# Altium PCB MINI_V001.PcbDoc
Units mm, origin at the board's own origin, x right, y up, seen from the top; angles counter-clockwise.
Board outline 42.31 x 45.25 mm, 2 copper layers (Top Layer, Bottom Layer); 51 components, 48 nets, 206 pads, 51 vias.
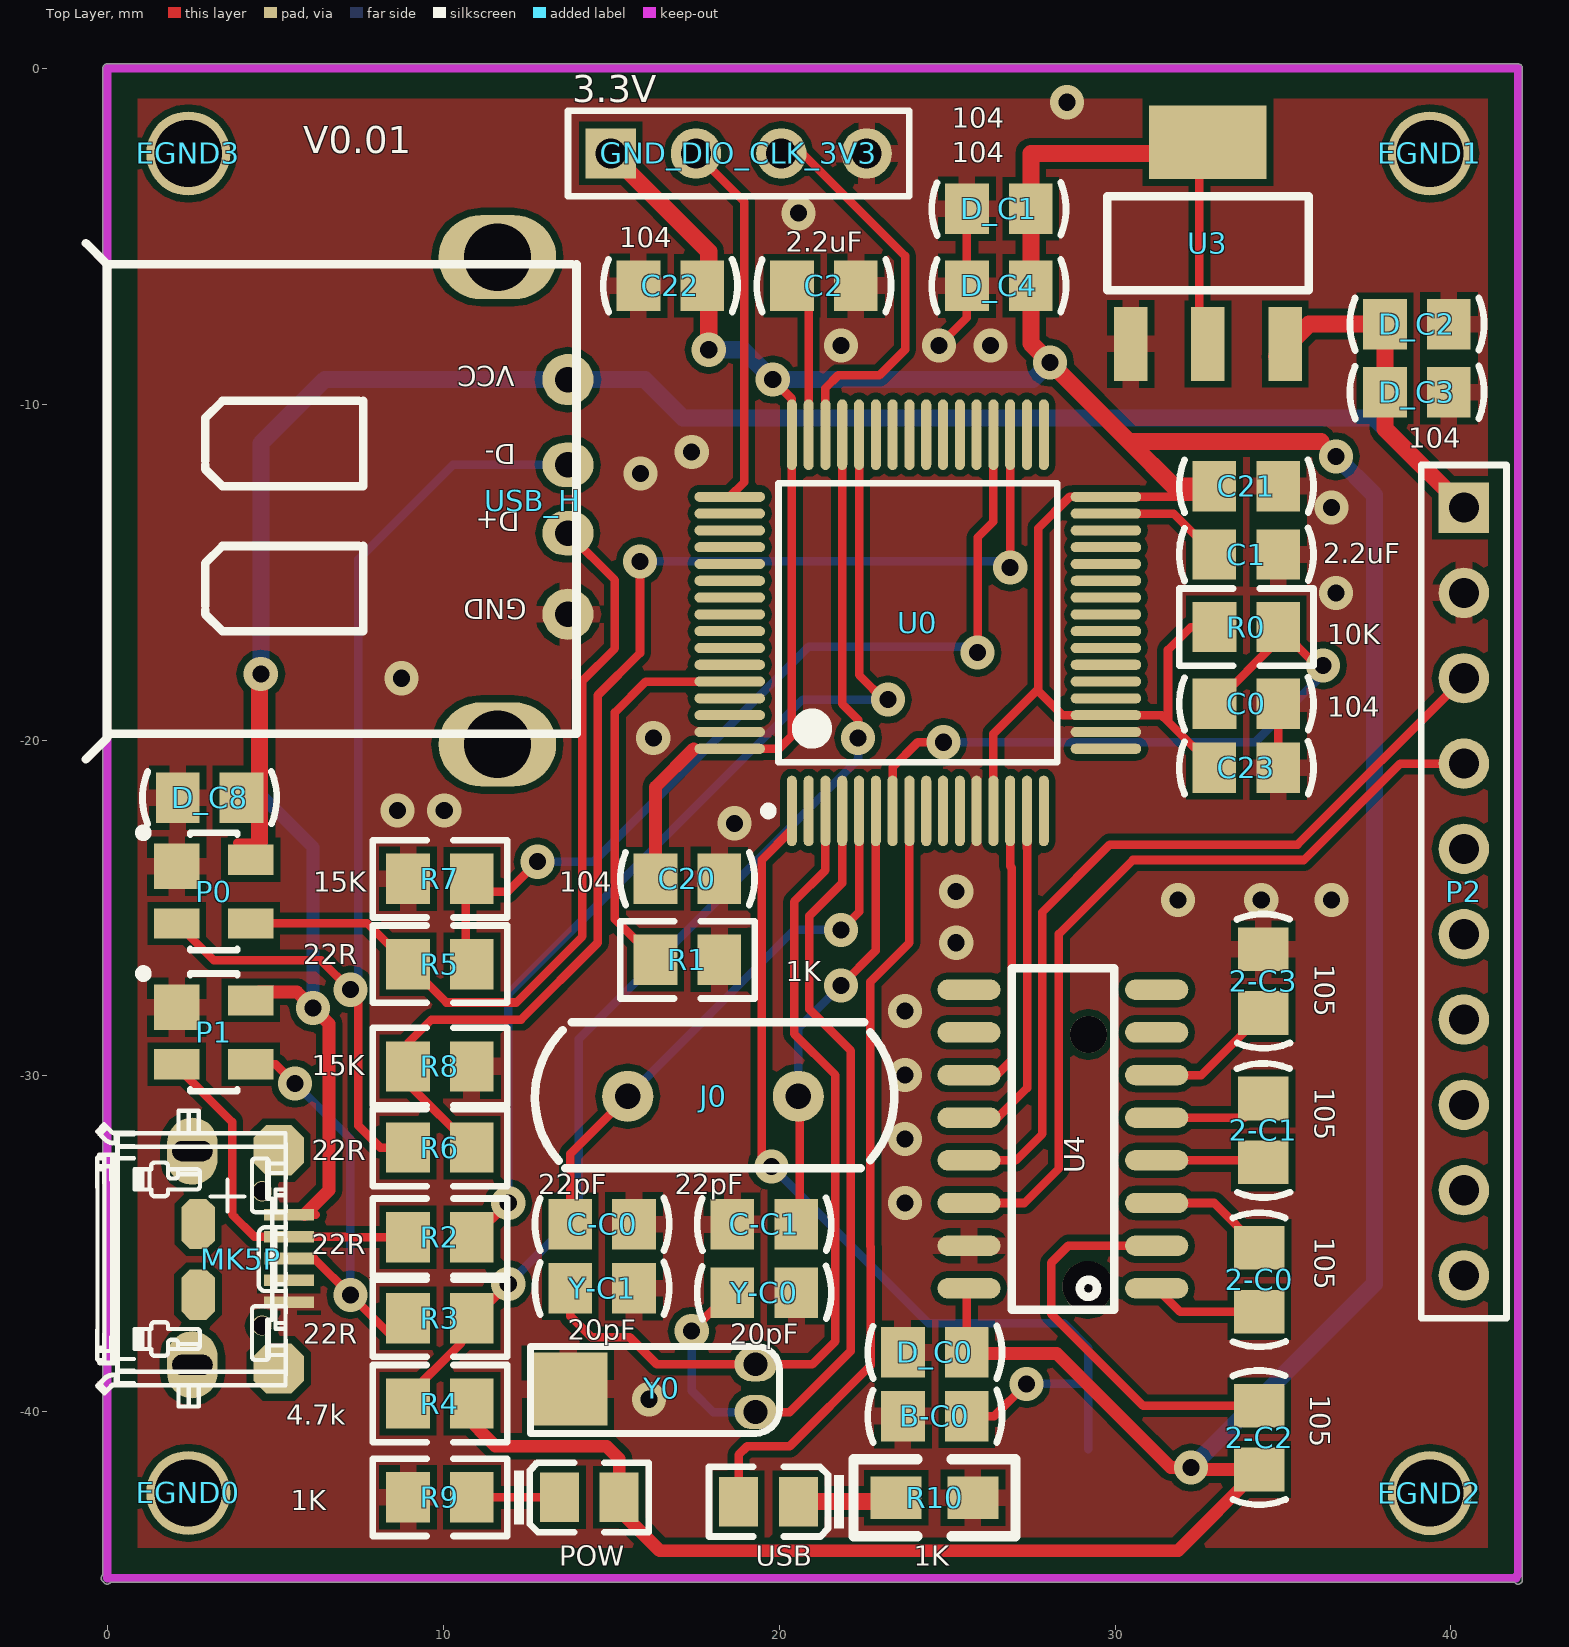
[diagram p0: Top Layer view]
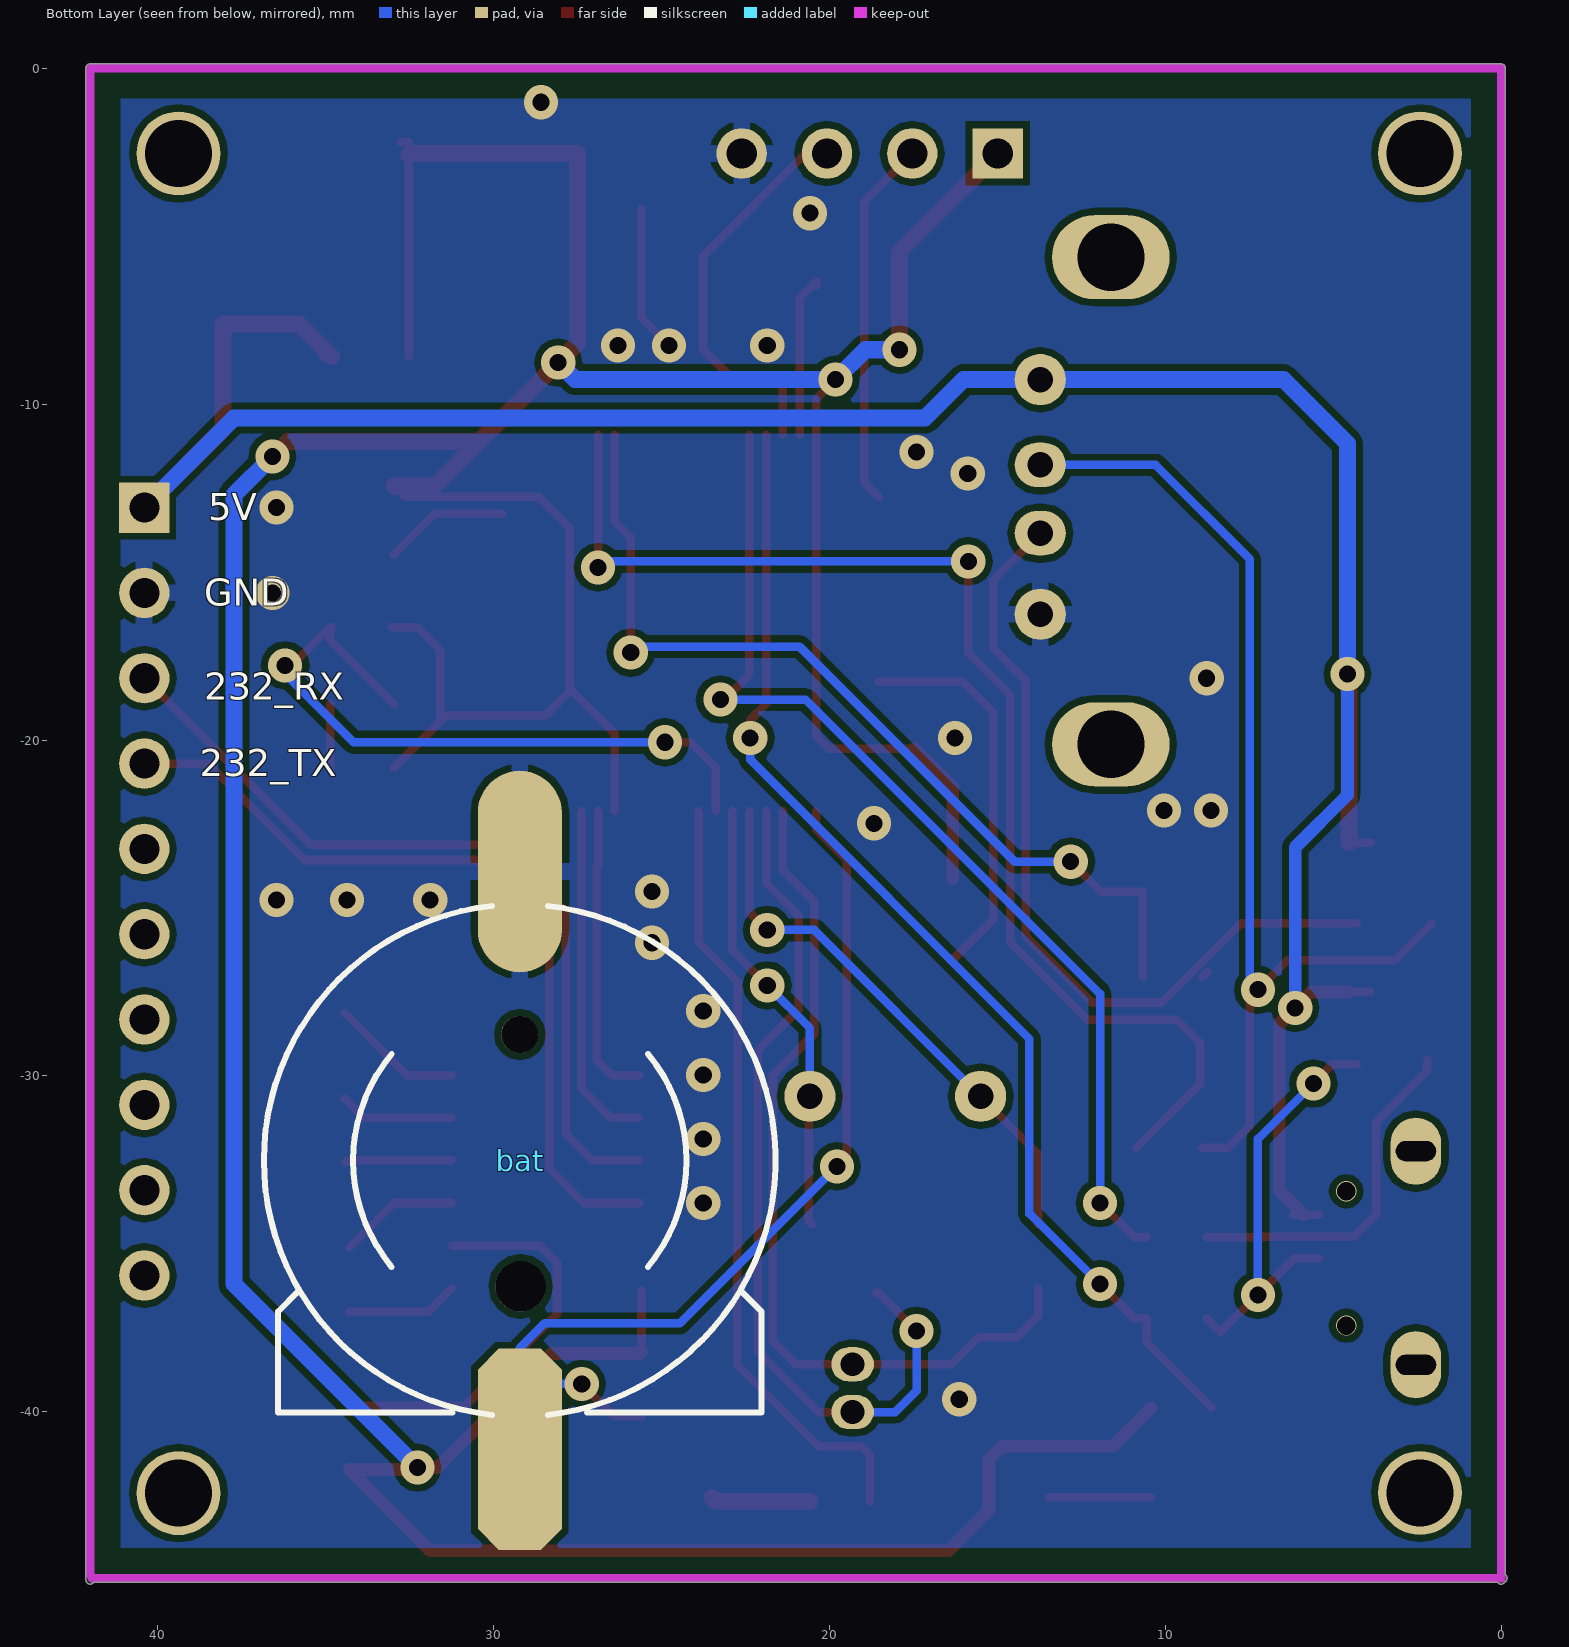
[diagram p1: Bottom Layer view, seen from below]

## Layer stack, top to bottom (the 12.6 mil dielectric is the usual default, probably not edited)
Top Layer: signal copper 0.0356
Dielectric: dielectric 0.32, FR-4, Dk 4.8
Bottom Layer: signal copper 0.0356

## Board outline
-0.112,-45.061 cw(c-0.051,-44.949) -0.127,-44.847 -0.127,0 cw(c0,0) 0,0.127 42,0.127 cw(c42,0) 42.127,0 42.127,-45 cw(c42,-45) 41.898,-45.077 0.102,-45.077 cw(c0,-45)

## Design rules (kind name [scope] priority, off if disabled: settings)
Clearance Clearance_keepout [(OnLayer('Keep-Out Layer'))] p1: gap=0.762
Clearance Clearance_ploy [inpoly] p2: gap=0.203
Clearance [All] p3: gap=0.152
ComponentClearance [All] p1: gap=0.127 collisioncheckmode=3 verticalgap=0.254 showdistances=FALSE
DiffPairsRouting DiffPair_DiffPairsRouting [InDifferentialPair ('VOUT2')] p1: maxlimit=0.254 minlimit=0.254 mostfreqgap=0.254 maxuncoupledlength=12.7
DiffPairsRouting [All] p2: maxlimit=0.254 minlimit=-0.044 mostfreqgap=0.254 toplayer_maxgap=-0.044 toplayer_prefgap=3.693 bottomlayer_maxgap=-0.044 bottomlayer_prefgap=2.348 maxuncoupledlength=12.7
HoleSize [All] p1: absolutevalues=TRUE maxlimit=5 minlimit=0.025 maxpercent=80.000 minpercent=20.000
HoleSize FabricationTestpoint [All] p2: absolutevalues=TRUE maxlimit=2.54 minlimit=0.025 maxpercent=80.000 minpercent=20.000
HoleSize FabricationTestPointUsage [All] p3: absolutevalues=TRUE maxlimit=2.54 minlimit=0.025 maxpercent=80.000 minpercent=20.000
Length [All] p1: maxlimit=152.4 minlimit=0
MatchedLengths DiffPair_MatchedLengths [InDifferentialPair ('VOUT2')] p1: tolerance=25.4 checknetsindiffpair=TRUE checkdiffpairvsdiffpair=TRUE checkothers=TRUE
MinimumSolderMaskSliver [All] p1: minsoldermaskwidth=0
MinimumSolderMaskSliver SilkToSolderMaskClearance [IsPad] p2: minsoldermaskwidth=0.254
NetAntennae AssemblyTestpoint [All] p1: netantennaetolerance=0
NetAntennae [All] p2: netantennaetolerance=0
NetAntennae AssemblyTestPointUsage [All] p3: netantennaetolerance=0
NetAntennae UnpouredPolygon [All] p4: netantennaetolerance=0
NetAntennae SilkToBoardRegionClearance [All] p5: netantennaetolerance=0
PlaneConnect [All] p1: planeconnectstyle=Direct reliefexpansion=0.508 reliefentries=4 reliefconductorwidth=0.254 reliefairgap=0.254
PolygonConnect PolygonConnect_VIA [ISVIA] p1: connectstyle=Direct reliefconductorwidth=0.254 reliefentries=4 polygonreliefangle="90 Angle"
PolygonConnect [All] p2: connectstyle=Relief reliefconductorwidth=0.508 reliefentries=4 polygonreliefangle="90 Angle"
RoutingVias [All] p1: holewidth=0.4 width=0.8 viastyle="Through Hole" minholewidth=0.3 minwidth=0.6 maxholewidth=1 maxwidth=2
SilkToSilkClearance [All] p1: silktosilkclearance=0
SilkscreenOverComponentPads [All] p1: minsilkscreentomaskgap=0.254
SolderMaskExpansion [All] p1: expansion=0.102
TestPointUsage [All] p1: valid=0 allowmultiple=FALSE
Testpoint [All] p1: side=15 testpointundercomponent=TRUE minsize=1.016 maxsize=2.54 preferedsize=1.524 minholesize=0 maxholesize=1.016 preferedholesize=0.813 testpointgrid=0.025 style=1023 order=0123456789
Width Width_VCC3.3 [InNet('G+3V3')] p1: maxlimit=2.54 minlimit=0.305 preferedwidth=0.305
Width DiffPair_Width [InDifferentialPair('VOUT2')] p2: maxlimit=0.254 minlimit=0.254 preferedwidth=0.254
Width [All] p3: maxlimit=2.54 minlimit=0.152 preferedwidth=0.203
16 further rules are at their usual default settings.

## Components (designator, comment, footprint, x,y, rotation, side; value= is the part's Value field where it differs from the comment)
2-C0 "105" C-RAD-0805 34.29,-36.068 r270 top
2-C1 "105" C-RAD-0805 34.417,-31.623 r270 top
2-C2 "105" C-RAD-0805 34.29,-40.767 r90 top
2-C3 "105" C-RAD-0805 34.417,-27.178 r270 top
B-C0 "C104" C-RAD-0805 24.638,-40.132 r0 top
bat "Battery" BATM 29.21,-32.512 r180 bottom
C0 "104" C-RAD-0805 33.909,-18.923 r0 top
C1 "2.2uF" C-RAD-0805 33.909,-14.478 r0 top
C2 "2.2uF" C-RAD-0805 21.336,-6.477 r0 top
C20 "104" C-RAD-0805 17.272,-24.13 r180 top
C21 "106" C-RAD-0805 33.909,-12.446 r180 top
C22 "104" C-RAD-0805 16.764,-6.477 r0 top
C23 "106" C-RAD-0805 33.909,-20.828 r180 top
C-C0 "22pF" C-RAD-0805 14.732,-34.417 r180 top
C-C1 "22pF" C-RAD-0805 19.558,-34.417 r0 top
D_C0 "106" C-RAD-0805 24.638,-38.227 r0 top
D_C1 "104" C-RAD-0805 26.543,-4.191 r0 top
D_C2 "106" C-RAD-0805 38.989,-7.62 r0 top
D_C3 "104" C-RAD-0805 38.989,-9.652 r0 top
D_C4 "104" C-RAD-0805 26.543,-6.477 r0 top (schematic designator D_C1)
D_C8 "106" C-RAD-0805 3.048,-21.717 r0 top (schematic designator D_C2)
EGND0 "1孔" HOLEx1 2.413,-42.412 r0 top
EGND1 "1孔" HOLEx1 39.37,-2.54 r0 top
EGND2 "1孔" HOLEx1 39.37,-42.418 r0 top
EGND3 "1孔" HOLEx1 2.413,-2.54 r0 top
GND_DIO_CLK_3V3 "Header 4" HDR1X4 14.986,-2.54 r0 top
J0 "25M" 晶振HC-49S 18.034,-30.607 r180 top
MK5P "五脚端子" USB-MICRO1 5.08,-35.433 r90 top
P0 "PRTR5V0U2X" SOT-143 3.175,-24.511 r270 top
P1 "PRTR5V0U2X" SOT-143 3.175,-28.702 r270 top
P2 "Header 10" HDR1X10 40.386,-13.081 r270 top
POW "Rled" 0805_LED_S1 14.351,-42.545 r0 top (schematic designator D0)
R0 "10K" R2012-0805 33.909,-16.637 r0 top
R1 "1K" R2012-0805 17.272,-26.543 r0 top
R2 "22R" R2012-0805 9.906,-34.798 r180 top
R3 "22R" R2012-0805 9.906,-37.211 r180 top
R4 "4.7k" R2012-0805 9.906,-39.751 r0 top
R5 "22R" R2012-0805 9.906,-26.67 r180 top
R6 "22R" R2012-0805 9.906,-32.131 r180 top
R7 "15K" R2012-0805 9.906,-24.13 r180 top
R8 "15K" R2012-0805 9.906,-29.718 r0 top
R9 "1K" R2012-0805 9.906,-42.545 r0 top
R10 "1K" 0805 25.781,-42.545 r180 top
U0 "STM32F205RBT6" LQFP-64 24.13,-16.51 r90 top
U3 "AMS1117-3.3" SOT-223 32.766,-5.207 r270 top
U4 "MAX3232" SOP-16 31.242,-36.322 r90 top
USB "Bled" 0805_LED_S1 19.685,-42.672 r180 top (schematic designator D1)
USB_H "五脚端子" USB 13.716,-9.271 r180 top
Y0 "32.768M" XTAL32 19.304,-40.005 r180 top
Y-C0 "20pF" C-RAD-0805 19.558,-36.449 r180 top
Y-C1 "20pF" C-RAD-0805 14.732,-36.322 r180 top

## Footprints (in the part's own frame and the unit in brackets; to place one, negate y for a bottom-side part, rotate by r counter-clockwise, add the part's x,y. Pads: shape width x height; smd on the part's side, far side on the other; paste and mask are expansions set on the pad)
0805 [mil]
  rect 60x50 smd: 1(0.41,0.4) 2(90.41,0.4)
  silkscreen extent -50,-45 140,45
0805_LED_S1 [mm]
  rect 1.16x1.47 smd: A(0.89,0) K(-0.89,0)
  silkscreen extent -2.25,-1.03 1.77,1.03, body extent -1.01,-0.62 1.01,0.62, height 1.1
BATM [mm]
  round 1.1 hole 1.1 unplated: 0(0,3.748)
  round 1.5 hole 1.5 unplated: 0(0.025,-3.752)
  oct 2.5x6 smd: 1(0,-8.602)
  oval 2.5x6 smd: 2(0,8.598)
  silkscreen extent -7.62,-7.58 7.62,7.57
C-RAD-0805 [mm] "贴片电容"
  rect 1.3x1.5 smd: 1(-0.95,0) 2(0.95,0)
  silkscreen extent -2,-0.79 2,0.79, body extent -1.27,-0.64 1.27,0.64, height 0.9
HDR1X4 [mm] "Connector; Header; 4 Position"
  rect 1.5x1.5 hole 0.9: 1(0,0)
  round 1.5 hole 0.9: 2(2.54,0) 3(5.08,0) 4(7.62,0)
  silkscreen extent -1.27,-1.27 8.89,1.27
HDR1X10 [mm] "Connector; Header; 10 Position"
  rect 1.5x1.5 hole 0.9: 1(0,0)
  round 1.5 hole 0.9: 2(2.54,0) 3(5.08,0) 4(7.62,0) 5(10.16,0) 6(12.7,0) 7(15.24,0) 8(17.78,0) 9(20.32,0) 10(22.86,0)
  silkscreen extent -1.27,-1.27 24.13,1.27
HOLEx1 [mm]
  round 2.5 hole 2: 1(0,0)
LQFP-64 [mm] "LQFP64"
  oval 2.1x0.3 smd: 1(-5.6,3.75) 2(-5.6,3.25) 3(-5.6,2.75) 4(-5.6,2.25) 5(-5.6,1.75) 6(-5.6,1.25) 7(-5.6,0.75) 8(-5.6,0.25) 9(-5.6,-0.25) 10(-5.6,-0.75) 11(-5.6,-1.25) 12(-5.6,-1.75) 13(-5.6,-2.25) 14(-5.6,-2.75) 15(-5.6,-3.25) 16(-5.6,-3.75) 33(5.6,-3.75) 34(5.6,-3.25) 35(5.6,-2.75) 36(5.6,-2.25) 37(5.6,-1.75) 38(5.6,-1.25) 39(5.6,-0.75) 40(5.6,-0.25) 41(5.6,0.25) 42(5.6,0.75) 43(5.6,1.25) 44(5.6,1.75) 45(5.6,2.25) 46(5.6,2.75) 47(5.6,3.25) 48(5.6,3.75)
  oval 0.3x2.1 smd: 17(-3.75,-5.6) 18(-3.25,-5.6) 19(-2.75,-5.6) 20(-2.25,-5.6) 21(-1.75,-5.6) 22(-1.25,-5.6) 23(-0.75,-5.6) 24(-0.25,-5.6) 25(0.25,-5.6) 26(0.75,-5.6) 27(1.25,-5.6) 28(1.75,-5.6) 29(2.25,-5.6) 30(2.75,-5.6) 31(3.25,-5.6) 32(3.75,-5.6) 49(3.75,5.6) 50(3.25,5.6) 51(2.75,5.6) 52(2.25,5.6) 53(1.75,5.6) 54(1.25,5.6) 55(0.75,5.6) 56(0.25,5.6) 57(-0.25,5.6) 58(-0.75,5.6) 59(-1.25,5.6) 60(-1.75,5.6) 61(-2.25,5.6) 62(-2.75,5.6) 63(-3.25,5.6) 64(-3.75,5.6)
  silkscreen extent -5.72,-4.15 4.15,4.57, body extent -5,-5 5,5, height 1.6
R2012-0805 [mm] "Thermistor; 2 Leads"
  rect 1.3x1.5 smd: 1(-0.95,0) 2(0.95,0)
  silkscreen extent -2,-1.15 2,1.15, body extent -1.02,-0.64 0.98,0.62
SOP-16 [mil]
  oval 24x74 smd: 1(0,0) 2(50,0) 3(100,0) 4(150,0) 5(200,0) 6(250,0) 7(300,0) 8(350,0) 9(350,220) 10(300,220) 11(250,220) 12(200,220) 13(150,220) 14(100,220) 15(50,220) 16(0,220)
  silkscreen extent -25,50 375,170, body extent -19,-5 367,223, height 69
SOT-143 [mm] "SOT-143; 4 Leads; Body 3 x 2.6 mm, inc. leads (LxW max)"
  rect 1.35x1.35 smd: 1(-0.75,-1.1)
  rect 0.9x1.35 smd: 2(0.95,-1.1) 3(0.95,1.1) 4(-0.95,1.1)
  silkscreen extent -1.87,-2.22 1.75,0.7
SOT-223 [mm]
  rect 2.2x1 smd: 1(3,-2.3) 2(3,0) 3(3,2.3)
  rect 2.2x3.5 smd: 2(-3,0)
  silkscreen extent -1.4,-3 1.4,3, body extent -3.49,-3.24 3.49,3.24, height 1.64
USB [mil]
  round 60 hole 30: 1(0,0) 4(0,275)
  oval 60x52.13 hole 30: 2(0,100) 3(0,180)
  oval 137.79x98.42 hole 78.74: VSS(82.68,427.44) VSS2(82.68,-143.43)
  silkscreen extent -10,-160 565,445, body extent -16,-173 539,449, height 250
USB-MICRO1 [mm] "USB AF/10.0 4P母座卷边SMT(前插后贴) H=6.8mm"
  rect 0.35x1.5 smd: 1(-1.3,-0.33) 2(-0.65,-0.33) 3(0,-0.33) 4(0.65,-0.33) 5(1.3,-0.33)
  oct 1.5x1.5 smd: ""(-3.275,-0.025) ""(3.225,-0.025)
  oval 2x1.5 hole 0.6 slot 1.2 at 90 deg: ""(-3.165,2.545) ""(3.195,2.545)
  oct 1.5x1 smd: ""(-1.075,2.375) ""(1.025,2.375)
  silkscreen extent -4.41,-0.23 4.4,5.39
XTAL32 [mil]
  oval 50x40 hole 28: 1(0,0) 2(0,-56)
  rect 92.13x86 smd: ""(220,-27)
  silkscreen extent -28,-77 264,25
晶振HC-49S [mil]
  round 60 hole 30: 1(100,0) 2(-100,0)
  silkscreen extent -212,-87 209,84, body extent -223,-93 223,90, height 138

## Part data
2-C0 2-C1 2-C2 2-C3: library part "0805 1uF (105) 10% 50V", "贴片电容"
B-C0: library part "Cap Semi", "Capacitor (Semiconductor SIM Model)"
bat: "Multicell Battery"
C0 D_C0 D_C1 D_C2 D_C3 D_C4 D_C8: library part "0805 100nF(104) 10% 50V", "贴片电容"
C1 C2: library part "0805 2.2uF (225) 20% 50V", "贴片电容"
C20 C21 C22 C23: library part Cap, "Capacitor"
C-C0 C-C1: library part "0603 22pF (220) 5% 50V", "贴片电容"
GND_DIO_CLK_3V3: "Header, 4-Pin"
J0: library part 晶振
P2: "Header, 10-Pin"
POW: library part "0805 红灯", "发光二极管"
R0 R2 R3 R4 R5 R6 R7 R8 R9 R10: library part "0805 1KΩ (1001) 1%", "贴片电阻"
R1: library part "0603 1KΩ (1001) 1%", "贴片电阻"
U0: "ARM Cortex-M3 32-bit MCU, 128 KB Flash, 64 KB Internal RAM, 51 I/Os, 64-pin LQFP, -40 to 85 degC, Tray"
U3: library part "SOT-223 AMS1117-3.3", "低压差线性稳压(LDO)"
USB: library part "0805 蓝灯", "发光二极管"
Y0: library part XTAL, "Crystal Oscillator"
Y-C0 Y-C1: library part "0805 20pF (200) 5% 50V", "贴片电容"

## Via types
v1: diameter 1.016, hole 0.508, Top Layer to Bottom Layer, 49 vias
v2: diameter 0.6, hole 0.55, Top Layer to Bottom Layer, 2 vias

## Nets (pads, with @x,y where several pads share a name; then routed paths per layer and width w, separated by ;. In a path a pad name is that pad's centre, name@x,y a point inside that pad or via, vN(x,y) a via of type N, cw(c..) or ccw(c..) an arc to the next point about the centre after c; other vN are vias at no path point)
BAT: B-C0.2 bat.1 U0.1 | length 29.8
  Top Layer w0.254: v1(19.771,-32.69) 19.482,-32.4 19.482,-23.571 20.38,-22.673 U0.1 ; B-C0.2 26.401,-40.132 v1(27.366,-39.167)
  Bottom Layer w0.254: v1(19.771,-32.69) 24.445,-37.363 28.473,-37.363 29.21,-38.1 bat.1@29.21,-39.167 ; v1(27.366,-39.167) bat.1@29.21,-39.167 ; bat.1 bat.1@29.21,-39.167
GND: 2-C3.1 B-C0.1 bat.2 C0.2 C1.2 C2.2 C20.1 C21.1 C22.1 C23.1 C-C0.1 C-C1.1 D_C0.1 D_C1.1 D_C2.2 D_C3.2 D_C4.1 D_C8.1 GND_DIO_CLK_3V3.4 MK5P.1 P0.1 P1.1 P2.2 R1.2 R7.2 R8.2 R9.1 R10.1 U0.12 U0.18 U0.63 U3.1 U4.15 USB_H.4 Y0. Y-C0.1 Y-C1.1 | length 6.3
  Top Layer w0.254: v1(24.765,-8.255) 25.593,-7.427 D_C4.1 D_C1.1 ; C23.1 C0.2
  other v1: 16.129,-39.624 23.749,-33.782 23.749,-31.877 23.749,-29.972 23.749,-28.067 25.273,-26.035 31.877,-24.765 34.353,-24.765 36.449,-24.765 25.273,-24.511 18.669,-22.479 8.636,-22.098 10.033,-22.098 16.256,-19.939 8.763,-18.161 36.576,-15.621 36.449,-13.081 15.875,-12.065 17.399,-11.43 21.844,-8.255 26.289,-8.255 20.574,-4.318 28.575,-1.016
IO2: P0.2 R6.2 USB_H.2 | length 31.8
  Top Layer w0.254: P0.2 3.175,-26.561 6.368,-26.561 v1(7.239,-27.432) ; v1@7.478,-27.432 7.478,-31.481 8.128,-32.131 R6.2@8.889,-32.131
  Bottom Layer w0.254: v1@7.478,-27.356 7.478,-14.62 10.287,-11.811 USB_H.2
IO3: P0.3 R5.2 USB_H.3 | length 24.9
  Top Layer w0.254: P0.3 7.747,-25.461 R5.2 10.099,-27.813 12.18,-27.813 14.148,-25.846 14.148,-18.237 15.113,-17.272 15.113,-15.24 USB_H.3 ; R5.2@8.732,-26.894 R5.2@8.889,-27.051
IO4: MK5P.4 P1.2 R2.2 | length 10.7
  Top Layer w0.254: P1.2@2.202,-29.525 2.202,-29.652 2.202,-29.852 3.719,-31.369 3.719,-34.123 ; 3.81,-34.214 3.719,-34.123 ; R2.2@8.762,-34.798 7.086,-34.798 7.071,-34.783 MK5P.4 4.379,-34.783 3.719,-34.123
IO5: MK5P.3 P1.3 R3.2 | length 13.3
  Top Layer w0.254: P1.3 5.014,-29.652 v1(5.588,-30.226) ; MK5P.3 6.157,-35.433 v1(7.239,-36.515) 8.349,-37.624 R3.2@8.762,-37.211
  Bottom Layer w0.254: v1(5.588,-30.226) 7.239,-31.877 7.239,-32.629 ; v1(7.239,-36.515) 7.239,-32.629 ; 7.239,-33.02 7.239,-32.629
LED0: U0.8 USB.A | length 23.4
  Top Layer w0.254: USB.A 18.795,-41.276 19.05,-41.021 20.32,-41.021 22.733,-38.608 22.733,-35.079 22.718,-35.064 22.718,-27.197 23.88,-26.035 U0.8
LED1: U0.9
Net2-C0_1: 2-C0.1 U4.3 | length 3.6
  Top Layer w0.254: U4.3 32.954,-33.782 2-C0.1
Net2-C0_2: 2-C0.2 U4.1 | length 3.3
  Top Layer w0.254: U4.1 31.938,-37.018 2-C0.2
Net2-C1_1: 2-C1.1 U4.5 | length 3.4
  Top Layer w0.254: U4.5 33.848,-31.242 2-C1.1
Net2-C1_2: 2-C1.2 U4.4 | length 3.2
  Top Layer w0.254: U4.4 34.356,-32.512 2-C1.2
Net2-C2_2: 2-C2.2 U4.2 | length 12.2
  Top Layer w0.254: U4.2 28.611,-35.052 28.103,-35.56 28.103,-37.084 30.836,-39.817 2-C2.2
Net2-C3_2: 2-C3.2 U4.6 | length 3.9
  Top Layer w0.254: U4.6 32.573,-29.972 2-C3.2
NetC1_1: C1.1 U0.31 | length 3.7
  Top Layer w0.254: U0.31 31.741,-13.26 C1.1
NetC2_1: C2.1 U0.47 | length 4.9
  Top Layer w0.254: C2.1 20.386,-6.35 20.449,-6.413 20.88,-6.844 U0.47
NetD0_K: POW.K R9.2 | length 3
  Top Layer w0.254: R9.2@10.415,-42.545 R9.2 POW.K
NetD1_K: R10.2 USB.K | length 3
  Top Layer w0.508: USB.K 23.368,-42.672 R10.2
NetR1_1: R1.1 U0.60 | length 11.7
  Top Layer w0.254: R1.1 15.113,-25.334 15.113,-19.177 16.03,-18.26 U0.60 ; R1.1@16.352,-26.513 R1.1@16.382,-26.543
NRST: C0.1 R0.2 U0.7 | length 20.9
  Top Layer w0.254: U0.7 23.38,-20.816 24.13,-20.066 v1(24.892,-20.066) ; C0.1 34.859,-17.023 R0.2 36.002,-17.78 v1(36.195,-17.78) 36.576,-17.78 v1@36.449,-17.653 ; R0.2@34.799,-16.637 R0.2@34.829,-16.667
  Bottom Layer w0.254: v1(24.892,-20.066) 34.163,-20.066 v1@36.322,-17.907
OSC32_IN: U0.3 Y0.2 Y-C1.2 | length 26.3
  Top Layer w0.254: Y-C1.2 13.782,-37.15 14.412,-37.78 15.555,-37.78 16.358,-38.583 Y0.2 20.991,-38.583 21.676,-37.897 21.676,-29.972 20.447,-28.743 20.447,-24.809 21.38,-23.876 U0.3
OSC32_OUT: U0.4 Y0.1 Y-C0.2 | length 26.2
  Top Layer w0.254: v1(17.399,-37.592) 18.542,-36.449 Y-C0.2 ; Y0.1 20.32,-40.005 22.134,-38.191 22.134,-29.246 20.904,-28.016 20.904,-25.233 21.88,-24.257 U0.4
  Bottom Layer w0.254: v1(17.399,-37.592) 17.399,-39.37 18.034,-40.005 Y0.1
OSC_IN: C-C0.2 J0.1 U0.5 | length 16.7
  Top Layer w0.254: C-C0.2 13.782,-32.319 J0.1 ; v1(21.844,-25.654) 22.38,-25.118 U0.5
  Bottom Layer w0.254: J0.1 20.447,-25.654 v1(21.844,-25.654)
OSC_OUT: C-C1.2 J0.2 U0.6 | length 13.3
  Top Layer w0.254: C-C1.2 20.61,-34.315 20.61,-30.643 J0.2 ; v1(21.844,-27.305) 22.88,-26.269 U0.6
  Bottom Layer w0.254: J0.2 20.574,-28.575 v1(21.844,-27.305)
RS232_RX: P2.3 U4.13 | length 25.6
  Top Layer w0.254: U4.13 27.051,-32.512 27.838,-31.725 27.838,-27.026 ; 27.838,-27.686 27.838,-27.026 ; P2.3@40.386,-18.542 P2.3 35.433,-23.114 29.845,-23.114 27.838,-25.121 27.838,-27.026
RS232_TX: P2.4 U4.14 | length 24.6
  Top Layer w0.254: U4.14 27.305,-33.782 28.33,-32.757 28.33,-27.296 ; 28.33,-27.686 28.33,-27.296 ; P2.4 38.493,-20.701 35.622,-23.571 30.531,-23.571 28.33,-25.772 28.33,-27.296
RS485_RE: U0.33
SD_CK: U0.53
SD_CMD: U0.54
SD_D0: U0.39
SD_D1: U0.40
SD_D2: U0.51
SD_D3: U0.52
SD_EXTI: U0.41
SW_CLK: GND_DIO_CLK_3V3.2 U0.49 | length 11.3
  Top Layer w0.254: GND_DIO_CLK_3V3.2 18.959,-3.973 18.959,-10.312 ; U0.49 18.959,-12.331 18.959,-10.312 ; 18.959,-10.033 18.959,-10.312
SWDIO: GND_DIO_CLK_3V3.3 U0.46 | length 12
  Top Layer w0.254: GND_DIO_CLK_3V3.3 20.701,-2.54 23.749,-5.588 23.749,-8.382 22.987,-9.144 21.761,-9.144 21.38,-9.525 U0.46
UART1_RX: U0.43
UART1_TX: U0.42
UART4_RX: U0.15 U4.12 | length 10.3
  Top Layer w0.254: U4.12 26.502,-31.242 27.381,-30.363 27.381,-23.216 27.38,-23.214 U0.15
UART4_TX: U0.14 U4.11 | length 8.9
  Top Layer w0.254: U4.11 26.477,-29.972 26.924,-29.525 26.924,-23.8 26.88,-23.756 U0.14
UART6_RX: U0.38
UART6_TX: U0.37
USB_D+: R3.1 R4.1 U0.45 | length 35.1
  Top Layer w0.254: R4.1@8.635,-39.878 8.635,-39.85 8.845,-39.64 10.542,-37.943 10.542,-37.211 R3.1 10.922,-37.211 v1(11.938,-36.195) ; U0.45 21.88,-18.923 22.352,-19.395 v1(22.352,-19.939)
  Bottom Layer w0.254: v1(11.938,-36.195) 14.039,-34.094 14.039,-28.898 22.352,-20.584 v1(22.352,-19.939)
USB_D-: R2.1 U0.44 | length 31.3
  Top Layer w0.254: R2.1@10.542,-34.798 R2.1 10.922,-34.798 v1(11.938,-33.782) ; U0.44 22.38,-18.062 23.177,-18.86 v1@23.368,-19.05
  Bottom Layer w0.254: v1(11.938,-33.782) 11.938,-27.559 20.701,-18.796 v1@22.987,-18.796
  other v1: 23.241,-18.796
USB_HD+: R5.1 R7.1 U0.36 | length 27.8
  Top Layer w0.254: R5.1@10.669,-27.051 10.669,-26.67 10.669,-24.511 10.856,-24.511 11.923,-24.511 v1(12.812,-23.622) ; v1(25.908,-17.399) 25.908,-13.97 26.38,-13.498 U0.36
  Bottom Layer w0.254: v1(12.812,-23.622) 14.478,-23.622 20.879,-17.221 23.531,-17.221 ; 23.241,-17.221 23.531,-17.221 ; v1(25.908,-17.399) 25.73,-17.221 23.531,-17.221
USB_HD-: R6.1 R8.1 U0.35 | length 37.7
  Top Layer w0.254: R6.1 8.956,-30.231 R8.1 8.956,-29.017 9.652,-28.321 12.319,-28.321 14.605,-26.035 14.605,-18.669 15.86,-17.414 v1(15.86,-14.681) ; v1(26.88,-14.859) U0.35
  Bottom Layer w0.254: v1(15.86,-14.681) 26.702,-14.681 v1(26.88,-14.859)
VCC_3.3V: 2-C2.1 C20.2 C21.2 C22.2 C23.2 D_C0.2 D_C1.2 D_C4.2 GND_DIO_CLK_3V3.1 POW.A R0.1 R4.2 U0.13 U0.19 U0.32 U0.48 U0.64 U3.2 U4.16 | length 163.6
  Top Layer w0.254: 17.459,-20.26 U0.64 20,-20.26 20.38,-19.88 U0.48 20.38,-9.839 v1(19.812,-9.271) ; D_C0.2 U4.16@25.588,-36.388 ; U0.13 26.38,-19.812 27.686,-18.506 ; U3.2@32.512,-8.588 32.512,-8.207 32.512,-2.588 32.512,-2.207 U3.2@32.766,-2.207 ; C23.2 31.577,-19.446 ; C21.2 32.645,-12.76 U0.32 28.651,-12.76 27.718,-13.693 27.718,-18.474 27.686,-18.506 ; R0.1@33.019,-16.637 R0.1 32.258,-16.637 31.577,-17.318 31.577,-19.446 ; 27.686,-18.506 28.44,-19.26 U0.19 31.391,-19.26 31.577,-19.446
  Top Layer w0.381: R4.2@10.415,-39.878 10.572,-40.035 11.558,-41.021 14.859,-41.021 15.241,-41.403 POW.A 15.241,-42.927 16.447,-44.133 31.875,-44.133 2-C2.1 v1@32.258,-41.717 ; C20.2 16.322,-21.397 17.459,-20.26 ; D_C0.2 25.626,-38.265 28.268,-38.265 31.659,-41.656 v1(32.258,-41.656)
  Top Layer w0.508: GND_DIO_CLK_3V3.1 17.907,-5.461 17.907,-6.477 v1(17.907,-8.382) v1@17.907,-8.509 ; U3.2@32.512,-2.588 32.464,-2.54 27.493,-2.54 D_C1.2 D_C4.2 27.493,-8.189 v1(28.067,-8.763) 30.416,-11.112 ; C21.2 31.75,-12.446 30.416,-11.112 ; 36.131,-11.112 30.416,-11.112
  Bottom Layer w0.508: v1(17.907,-8.382) 18.923,-8.382 v1(19.812,-9.271) 27.559,-9.271 v1(28.067,-8.763) ; v1(32.258,-41.656) 37.719,-36.195 37.719,-12.7 v1(36.576,-11.557)
VCC_5V: D_C2.1 D_C3.1 D_C8.2 MK5P.5 P0.4 P1.4 P2.1 U3.3 USB_H.1 | length 81.9
  Top Layer w0.254: 3.871,-23.053 4.275,-23.053 4.529,-23.053 ; P1.4@3.896,-27.498 4.275,-27.498 P1.4@4.529,-27.498 ; MK5P.5 5.872,-34.133 6.208,-34.133 ; U3.3@34.812,-8.588 35.066,-8.588 35.066,-8.334 U3.3
  Top Layer w0.381: P1.4@4.529,-27.498 5.654,-27.498 v1(6.129,-27.973) 6.604,-28.448 6.604,-33.401 MK5P.5@5.872,-34.133
  Top Layer w0.508: 4.529,-23.053 4.529,-21.717 v1@4.529,-18.034 ; U3.3@34.812,-8.588 35.066,-8.334 35.13,-8.27 35.78,-7.62 D_C2.1 D_C3.1 38.039,-10.734 P2.1
  Bottom Layer w0.381: v1(4.572,-18.034) 4.572,-21.633 6.129,-23.19 v1(6.129,-27.973)
  Bottom Layer w0.508: v1(4.572,-18.034) 4.572,-11.176 6.477,-9.271 USB_H.1 16.002,-9.271 17.145,-10.414 37.719,-10.414 P2.1
pads on no net: bat.0 EGND0.1 EGND1.1 EGND2.1 EGND3.1 MK5P. MK5P.2 P2.5 P2.6 P2.7 P2.8 P2.9 P2.10 U0.2 U0.10 U0.11 U0.16 U0.17 U0.20 U0.21 U0.22 U0.23 U0.24 U0.25 U0.26 U0.27 U0.28 U0.29 U0.30 U0.34 U0.50 U0.55 U0.56 U0.57 U0.58 U0.59 U0.61 U0.62 U4.7 U4.8 U4.9 U4.10 USB_H.VSS USB_H.VSS2
copper on no net:
  other v2: 4.61,-37.433 4.61,-33.433

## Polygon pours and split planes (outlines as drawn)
GND on Top Layer "Top Layer-No Net" (solid): 0,0 42,0 42,-44.898 41.949,-44.949 41.831,-44.831 0,-44.831
GND on Bottom Layer "Top Layer-No Net" (solid): 0,0 42,0 41.949,-0.051 41.949,-44.898 0.051,-44.898 0,-44.949

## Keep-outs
Keep-Out Layer:
  lines w0.1: 0,0 42,0
  lines w0.254: 0,-44.949 41.949,-44.949 41.949,-44.898 42,-44.847 42,0 0,0 0,-44.949

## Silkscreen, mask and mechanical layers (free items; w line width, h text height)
Top Overlay:
  text "3.3V" at 13.843,-1.016 h0.8
  text "V0.01" at 5.842,-2.54 h0.8
Bottom Overlay:
  text "5V" at 38.481,-13.462 h0.8
  text "GND" at 38.608,-16.002 h0.8
  text "232_RX" at 38.608,-18.796 h0.8
  text "232_TX" at 38.735,-21.082 h0.8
